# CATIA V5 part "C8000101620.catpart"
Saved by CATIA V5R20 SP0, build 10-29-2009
Part number: C8000101620
Source: Unknown
Property "A": "30"
Property "ARTICLENO": "C8000101620"
Property "B": "13"
Property "BOMINFO": "C8000101620"
Property "C": "46"
Property "CA": "C8000101620"
Property "D1": "38"
Property "DES": "ROTATING EYEBOLT WITH RING Ton 1,12 M16x20"
Property "E": "50"
Property "H": "105"
Property "L": "20"
Property "LINA": "C8000101620"
Property "NB": "C8000101620"
Property "NBSYN": "$CODE."
Property "NN": "C800"
Property "NT": "Rotating eyebolt with ring"
Property "SIZE": "M16"
Property "SUPPLIER": "CF"
Property "SW": "30"
Property "WEIGHT": "530"
Property "WLL": "1.12"
Bounding box of the stored display mesh (mm): x -27.837 to 28, y -20 to 117.837, z -19 to 19
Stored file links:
  C:\Users\Utente\Desktop\3D files 800\C8000101620.catpart
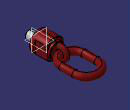
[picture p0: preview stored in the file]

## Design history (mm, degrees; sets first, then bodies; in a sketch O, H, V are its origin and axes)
Body1 "Geometry.1" (main body)
  Solid1 "C8000101620.catpart": solid without history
